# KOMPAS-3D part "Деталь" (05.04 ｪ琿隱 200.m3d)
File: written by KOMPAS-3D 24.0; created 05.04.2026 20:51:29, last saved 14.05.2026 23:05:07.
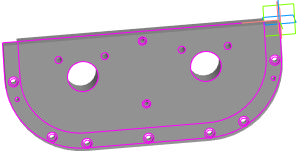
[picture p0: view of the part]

Document properties: Автор: taras; Полное имя файла: E:\test_kompas\all_v22\05.04 крышка200.m3d

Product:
- Part/product: Деталь
    Масса: 19.948382

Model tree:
1. Эскиз:3
2. Элемент выдавливания:24
     Расстояние 1 = 20
3. Элемент выдавливания:25
     Расстояние 1 = -20
4. Эскиз:4  (with: Грань.Элемент выдавливания:24, Вершина.Элемент выдавливания:24)
5. Элемент выдавливания:26
     Расстояние 1 = -40
6. Элемент выдавливания:27
     Расстояние 1 = -40
7. Элемент выдавливания:28
     Расстояние 2 = 40
8. Элемент выдавливания:29
     Расстояние 2 = 11
9. Элемент выдавливания:30
     Расстояние 2 = 20
10. Элемент выдавливания:31
     Расстояние 2 = 20
11. Элемент выдавливания:32
     Расстояние 2 = 30
12. Элемент выдавливания:35
     Расстояние 2 = 20
13. Элемент выдавливания:36
     Расстояние 2 = 10
14. Элемент выдавливания:37
     Расстояние 2 = 40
